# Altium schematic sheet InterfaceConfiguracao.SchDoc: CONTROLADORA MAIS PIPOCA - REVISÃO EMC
size A3; DocumentNumber: GA0078; SheetNumber: 10; SheetTotal: 17
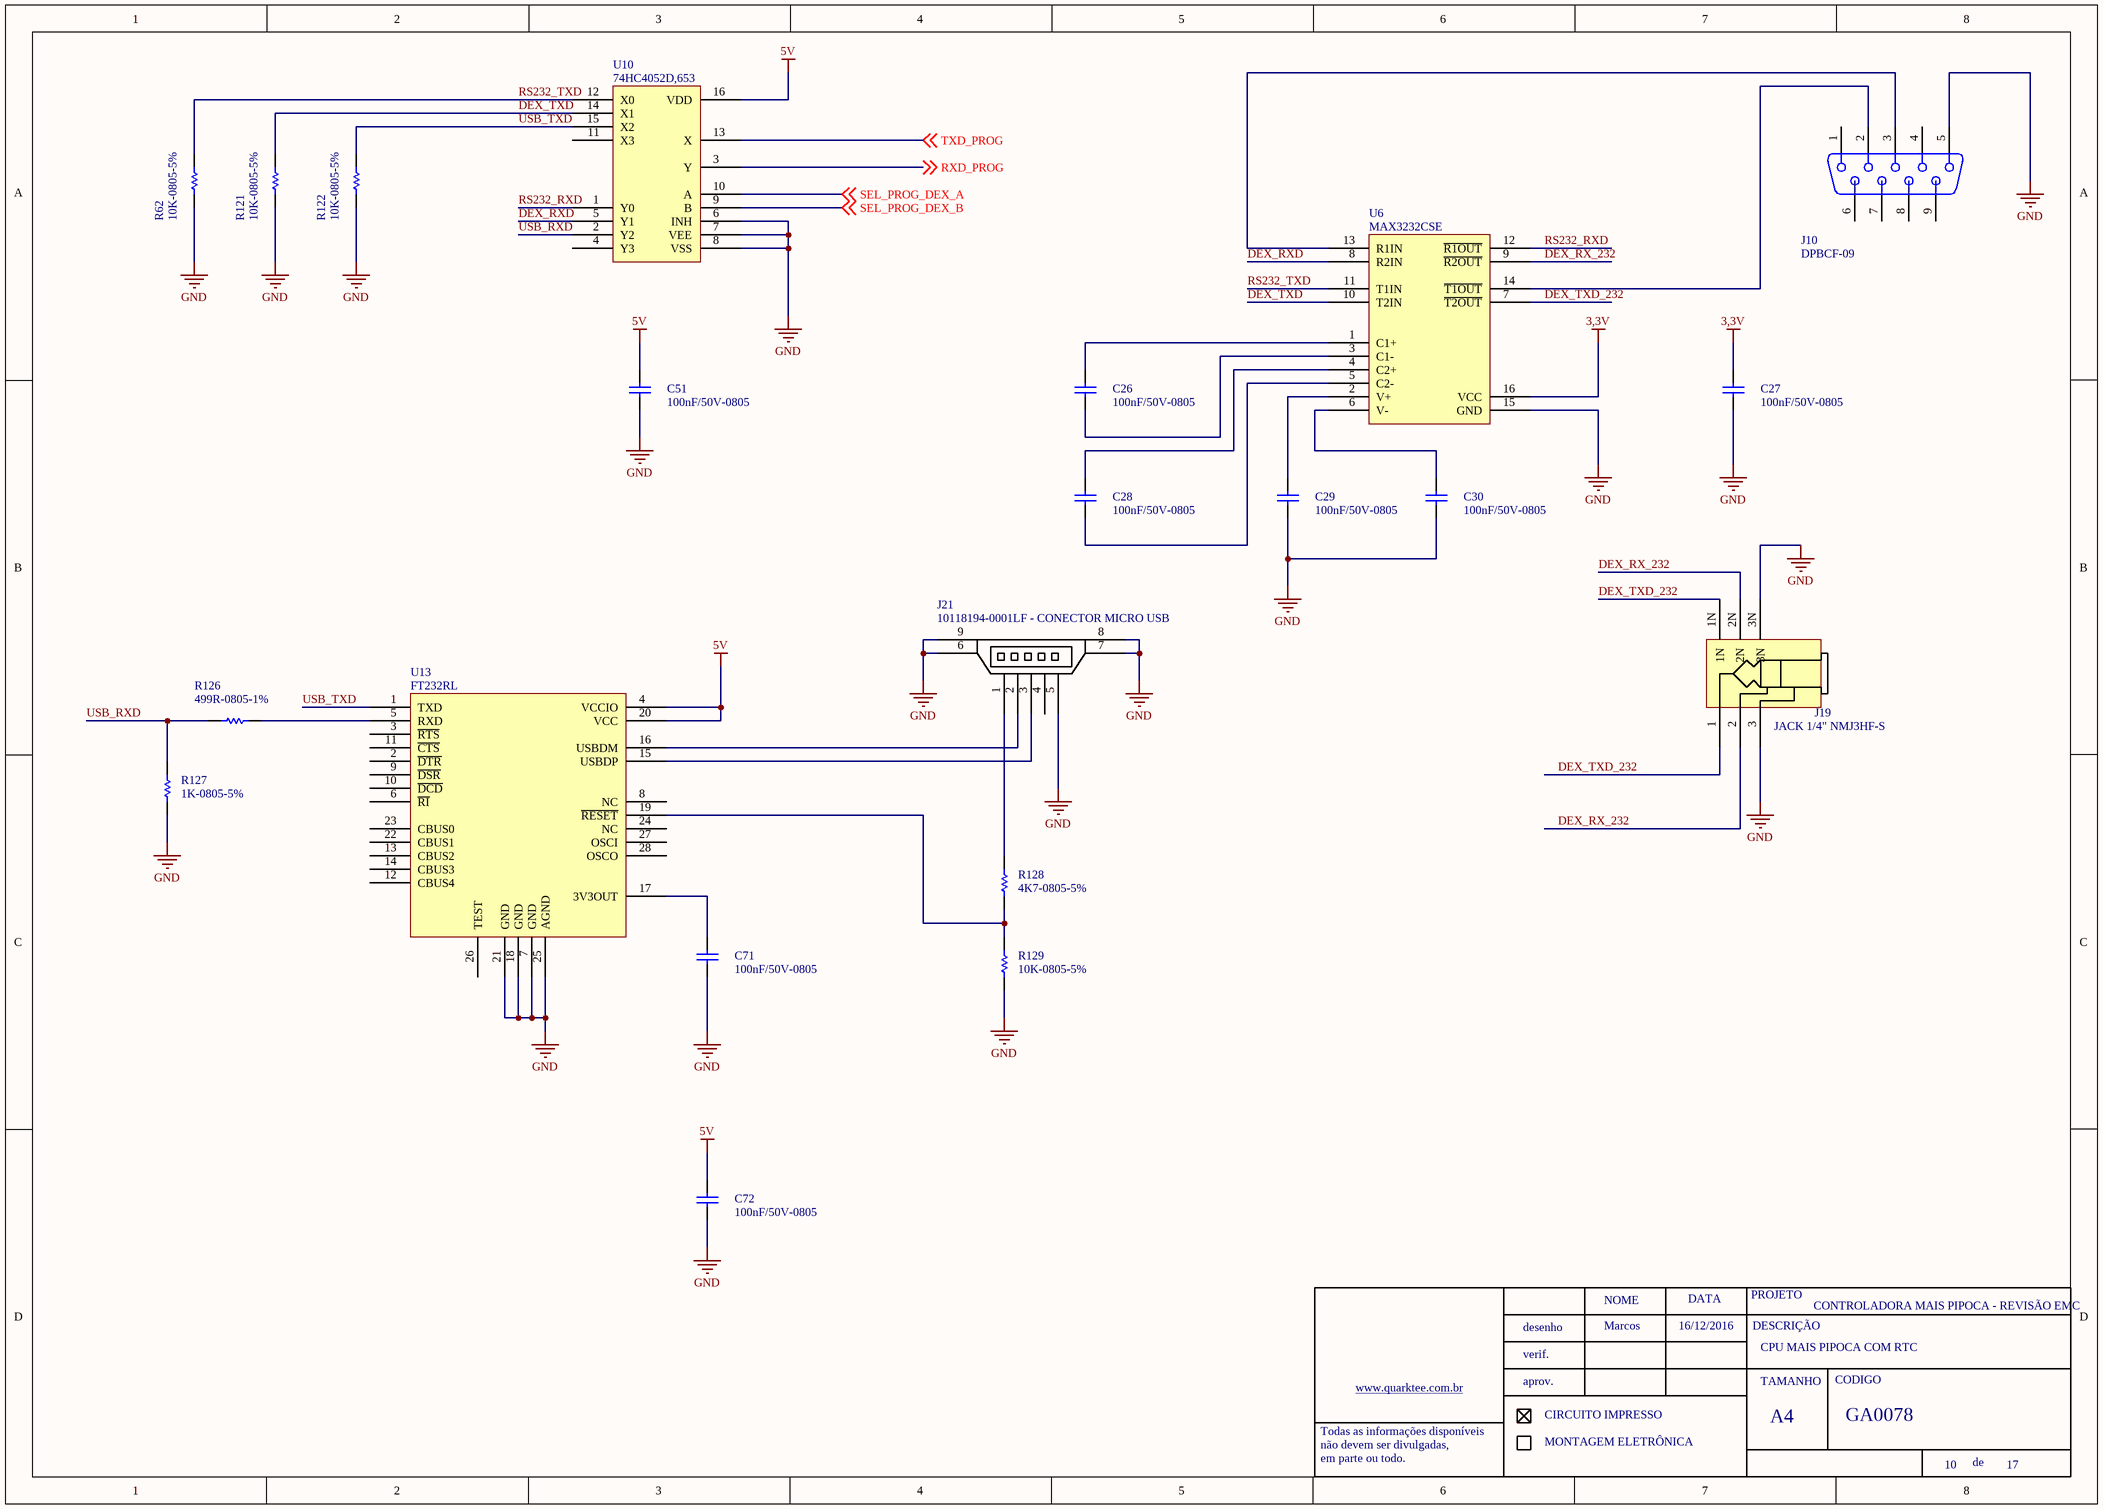
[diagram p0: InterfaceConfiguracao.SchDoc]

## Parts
C26  100nF/50V-0805  [0805-REVISADO ONDA]
C27  100nF/50V-0805  [0805-REVISADO ONDA]
C28  100nF/50V-0805  [0805-REVISADO ONDA]
C29  100nF/50V-0805  [0805-REVISADO ONDA]
C30  100nF/50V-0805  [0805-REVISADO ONDA]
C51  100nF/50V-0805  [0805-REVISADO ONDA]
C71  100nF/50V-0805  [0805-REVISADO ONDA]
C72  100nF/50V-0805  [0805-REVISADO ONDA]
J10  DPBCF-09  [DB9-FÊMEA MONTAGEM EM PCI 180]
J19  JACK 1/4" NMJ3HF-S
J21  10118194-0001LF - CONECTOR MICRO USB
R62  10K-0805-5%  [0805-REVISADO ONDA]
R121  10K-0805-5%  [0805-REVISADO ONDA]
R122  10K-0805-5%  [0805-REVISADO ONDA]
R126  499R-0805-1%  [0805-REVISADO ONDA]
R127  1K-0805-5%  [0805-REVISADO ONDA]
R128  4K7-0805-5%  [0805-REVISADO ONDA]
R129  10K-0805-5%  [0805-REVISADO ONDA]
U6  MAX3232CSE  [SOIC 16 PINOS]
U10  74HC4052D,653
U13  FT232RL

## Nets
3,3V: C27.2 U6.16(VCC)
5V: C51.2 C72.2 U10.16(VDD) U13.4(VCCIO) U13.20(VCC)
GND: C27.1 C29.1 C30.1 C51.1 C71.1 C72.1 J10.5 J19.3 J19.3N J21.5 J21.6 J21.7 J21.8 J21.9 R62.1 R121.1 R122.1 R127.1 R129.1 U6.15(GND) U10.6(INH) U10.7(VEE) U10.8(VSS) U13.7(GND) U13.18(GND) U13.21(GND) U13.25(AGND)
DEX_RX_232: J19.2 J19.2N U6.9(~{R2OUT})
DEX_RXD: U6.8(R2IN) U10.5(Y1)
DEX_TXD: R121.2 U6.10(T2IN) U10.14(X1)
DEX_TXD_232: J19.1 J19.1N U6.7(~{T2OUT})
RS232_RXD: U6.12(~{R1OUT}) U10.1(Y0)
RS232_TXD: R62.2 U6.11(T1IN) U10.12(X0)
RXD_PROG: U10.3(Y) ; off-sheet RXD_PROG
SEL_PROG_DEX_A: U10.10(A) ; off-sheet SEL_PROG_DEX_A
SEL_PROG_DEX_B: U10.9(B) ; off-sheet SEL_PROG_DEX_B
TXD_PROG: U10.13(X) ; off-sheet TXD_PROG
USB_RXD: R126.1 R127.2 U10.2(Y2)
USB_TXD: R122.2 U10.15(X2) U13.1(TXD)
NetC26_1: C26.1 U6.3(C1-)
NetC26_2: C26.2 U6.1(C1+)
NetC28_1: C28.1 U6.5(C2-)
NetC28_2: C28.2 U6.4(C2+)
NetC29_2: C29.2 U6.2(V+)
NetC30_2: C30.2 U6.6(V-)
NetC71_2: C71.2 U13.17(3V3OUT)
NetJ10_2: J10.2 U6.14(~{T1OUT})
NetJ10_3: J10.3 U6.13(R1IN)
NetJ21_1: J21.1 R128.2
NetJ21_2: J21.2 U13.16(USBDM)
NetJ21_3: J21.3 U13.15(USBDP)
NetR126_2: R126.2 U13.5(RXD)
NetR128_1: R128.1 R129.2 U13.19(~{RESET})

Not connected (* = marked no-connect by the designer): J10 1 4 6 7 8 9; J21 4; U10 4(Y3) 11(X3); U13 2(~{DTR}) 3(~{RTS}) 6(~{RI}) 8(NC) 9(~{DSR}) 10(~{DCD}) 11(~{CTS}) 12(CBUS4) 13(CBUS2) 14(CBUS3) 22(CBUS1) 23(CBUS0) 24(NC) 26(TEST) 27(OSCI) 28(OSCO)

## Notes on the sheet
- Marcos
- 16/12/2016
- CPU MAIS PIPOCA COM RTC

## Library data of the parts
C26-C30 C51 C71 C72 = 100nF/50-0805-NPO
J10 = DB-9 - FÊMEA 180º MONTAGEM EM PCI: DBPCF-09
J19 = NMJ3HF-S
J21 = MINI_USB
R126 = 1K-0805-5%
R128 = 10K-0805-5%
U10 = CD74HC4052PWR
